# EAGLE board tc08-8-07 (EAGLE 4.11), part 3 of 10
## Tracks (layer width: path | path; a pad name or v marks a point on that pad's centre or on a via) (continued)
DB_03\  (via drill 0.61) (continued)
  Bottom 0.254: v309.28,75.87 309.92,76.5 310.55,76.5 313.41,79.36 313.41,84.44 v314.36,84.44 | v318.49,88.57 321.66,91.74 322.3,91.74 v323.25,92.7 | v328.97,98.73 330.55,97.14 334.05,97.14 334.36,97.46 337.22,97.46 337.54,97.14 341.03,97.14 344.21,100.32 v344.21,101.91 | v353.41,116.83 353.41,119.37 354.68,119.37 v356.27,120.96 | v350.87,146.67 v353.73,146.67 | v350.56,172.07 349.92,172.71 346.75,172.71 346.11,173.34 346.11,177.47 347.06,177.47 B02.L1 347.38,178.42 347.06,178.42 v347.06,181.28 | v300.39,254.94 302.93,252.4 v306.11,252.4 | v305.47,248.59 308.01,246.05 315.63,246.05 318.81,242.87 323.57,242.87 327.06,239.38 333.09,239.38 334.68,237.8 v336.27,237.8
DB_04\  (via drill 0.61)
  Top 0.254: 295.31,232.08 295.31,248.27 296.58,249.54 296.58,253.35 A06.J1 | 295.31,232.08 295.31,220.97 296.26,220.02 296.26,205.09 295.63,204.46 295.63,177.15 294.99,176.52 294.99,163.5 295.31,163.18 295.31,142.86 295.63,142.55 295.63,137.78 295.31,137.46 295.31,119.69 294.99,119.37 294.99,88.89 296.26,87.62 296.26,71.43 295.31,70.47 295.31,56.82 296.26,55.87 296.26,51.74 296.58,51.42 D06.J1 | v358.18,192.08 358.49,192.39 358.49,194.61 358.18,194.93 358.18,199.06 358.81,199.7 358.81,200.33 354.05,205.09 v354.05,210.17 | v330.87,210.81 331.19,211.12 331.19,221.92 329.28,223.83 v329.28,226.68 | v295.63,232.08 295.31,232.08
  Bottom 0.254: v358.18,192.08 361.67,192.08 361.67,188.9 359.13,186.36 359.13,182.87 362.3,179.69 364.84,179.69 364.84,167.63 363.57,166.36 349.29,166.36 348.33,165.4 B02.R1 | v354.05,210.17 353.73,209.86 331.82,209.86 v330.87,210.81 | v329.28,226.68 328.97,227 317.22,227 316.9,227.32 310.23,227.32 309.92,227 304.52,227 304.2,227.32 301.98,227.32 297.22,232.08 v295.63,232.08
DB_05\  (via drill 0.61)
  Top 0.254: v306.11,55.55 308.33,57.77 308.33,62.85 308.01,63.17 308.01,64.44 v310.23,66.66 | v334.05,117.78 333.73,118.1 333.73,123.18 334.36,123.81 v334.36,124.13 | v350.24,159.69 350.56,160.01 350.56,161.28 B02.S1 350.56,162.55 350.56,165.09 v350.24,165.4 | v288.01,253.35 286.1,255.26 286.1,280.66 288.01,282.56 v288.01,288.6 | v368.65,282.56 369.61,281.61 v369.61,250.81 | v361.03,243.83 359.13,241.92 359.13,240.65 359.76,240.02 v359.76,237.48
  Route2 0.254: v310.23,66.66 311.82,68.25 311.82,70.16 314.36,72.69 314.36,75.24 315,75.87 315,82.54 315.31,82.86 315.31,86.35 317.22,88.25 317.22,98.41 319.44,100.63 319.76,100.63 321.03,101.91 321.03,102.22 322.3,103.49 322.3,104.44 329.6,111.75 329.6,113.33 v334.05,117.78 | v334.36,124.13 334.36,125.72 332.78,127.3 332.78,129.21 333.09,129.53 333.09,135.88 339.44,142.23 339.44,147.62 345.48,153.66 345.48,154.61 350.24,159.37 v350.24,159.69 | v360.08,193.03 360.08,192.08 v358.18,190.17 | v350.24,165.4 v357.22,172.39
  Route15 0.254: v359.76,237.48 356.59,234.3 358.49,232.4 358.49,227.64 v360.08,226.05 | v358.18,221.92 361.99,218.11 361.99,204.46 v365.48,200.96
  Bottom 0.254: v306.11,55.55 305.15,55.55 305.15,50.79 300.39,46.03 298.8,46.03 297.53,44.75 D06.L1 | v288.01,253.35 289.28,253.35 289.28,249.86 288.96,249.54 288.96,247.32 290.23,246.05 294.99,246.05 296.26,247.32 A06.L1 | v288.01,288.6 288.33,288.91 321.66,288.91 321.98,288.6 362.62,288.6 v368.65,282.56 | v369.61,250.81 369.61,241.92 369.92,241.61 369.92,240.33 368.65,240.33 367.7,241.29 367.7,243.51 364.53,243.51 364.21,243.19 362.94,243.19 362.3,243.83 v361.03,243.83 | v360.08,226.05 360.08,223.51 359.76,223.51 v358.18,221.92 | v365.48,200.96 365.48,198.43 360.08,198.43 358.81,197.15 358.81,193.03 v360.08,193.03 | v358.18,190.17 355.64,187.63 355.64,173.66 355.95,173.66 v357.22,172.39
DB_06\  (via drill 0.61)
  Top 0.254: v292.77,6.97 292.77,7.29 301.34,15.86 301.34,35.55 300.07,36.82 D06.M1 | v3.85,40.95 2.89,41.9 2.89,222.55 3.53,223.19 3.53,248.91 2.26,250.18 2.26,267.64 2.89,268.28 2.89,269.55 v2.58,269.86 | v130.53,296.22 138.47,296.22 138.47,296.53 139.1,297.17 142.28,297.17 142.28,277.17 143.23,276.21 143.23,272.4 v144.82,270.81 | v155.61,270.18 157.52,270.18 157.83,270.5 159.1,270.5 159.1,269.23 160.37,267.96 165.77,267.96 165.77,267.64 167.36,266.05 168.63,266.05 168.63,273.99 170.85,276.21 170.85,293.99 171.17,294.31 176.57,294.31 176.57,284.47 v184.19,276.85 | v189.58,277.8 197.2,277.8 197.52,278.12 209.59,278.12 v209.59,276.53 | v260.07,286.69 259.43,286.05 259.43,275.9 v259.12,275.58 | v267.69,271.77 v268.96,273.04 | v343.25,198.11 342.94,198.43 342.94,200.33 345.79,203.19 345.79,205.73 346.11,206.05 346.11,210.17 345.16,211.12 v345.16,222.87
  Route2 0.254: v184.19,276.85 184.5,276.85 185.14,277.48 189.27,277.48 v189.58,277.8 | v278.17,270.18 278.17,268.91 276.58,267.32 276.58,262.56 v274.99,260.97
  Route15 0.254: v209.59,276.53 212.76,279.7 228.95,279.7 239.75,290.5 242.92,287.32 242.92,286.69 v241.97,285.74 | v259.12,275.58 261.34,273.36 v261.66,273.36 | v287.37,259.07 298.17,248.27 298.17,246.68 299.76,245.1 A06.M1
  Bottom 0.254: v292.77,6.97 292.45,6.66 275.94,6.66 275.63,6.34 261.02,6.34 259.75,5.07 232.13,5.07 230.22,6.97 223.56,6.97 222.92,6.34 38.45,6.34 v3.85,40.95 | v2.58,269.86 2.58,292.72 52.42,292.72 53.38,293.68 63.85,293.68 64.49,293.04 81.32,293.04 82.59,294.31 97.51,294.31 98.14,294.94 103.54,294.94 104.18,294.31 128.62,294.31 v130.53,296.22 | v144.82,270.81 145.13,271.13 154.66,271.13 v155.61,270.18 | v241.97,285.74 242.61,286.37 248.32,286.37 248.64,286.69 v260.07,286.69 | v261.66,273.36 261.97,273.04 263.24,273.04 264.51,271.77 v267.69,271.77 | v268.96,273.04 270.23,271.77 273.4,271.77 274.04,272.4 275.94,272.4 v278.17,270.18 | v274.99,260.97 276.9,259.07 v287.37,259.07 | v343.25,198.11 343.25,194.93 340.08,191.76 340.08,189.22 341.35,187.95 343.57,187.95 343.89,187.63 B02.H2 | v345.16,222.87 343.25,224.78 340.71,224.78 335,230.49 330.87,230.49 330.55,230.81 328.65,230.81 328.33,231.13 326.74,231.13 325.79,230.18 316.27,230.18 315.95,229.86 314.68,229.86 313.41,228.59 312.14,228.59 300.39,240.33 300.39,243.83 A06.M1
DB_07\  (via drill 0.61)
  Top 0.254: D06.P1 299.76,35.55 299.12,36.18 299.12,40.31 298.8,40.63 298.8,46.98 298.17,47.61 298.17,56.5 298.8,57.14 298.8,66.03 298.49,66.35 298.49,75.87 300.07,77.46 300.07,90.16 298.8,91.43 v298.8,183.18 298.8,209.22 300.07,210.49 300.07,223.51 298.8,224.78 298.8,232.71 299.76,233.67 299.76,237.48 A06.P1
  Bottom 0.254: v298.8,183.18 301.03,183.18 301.66,182.55 309.92,182.55 310.87,183.5 313.41,183.5 314.04,182.87 339.76,182.87 340.71,183.82 B02.J2
DB_08\  (via drill 0.61)
  Top 0.254: v294.36,11.42 298.8,15.86 298.8,22.85 299.12,23.16 299.12,27.29 299.76,27.93 D06.S1 | v100.68,14.59 98.14,17.13 98.14,154.93 98.46,155.24 98.46,157.47 98.14,157.79 98.14,202.24 97.83,202.55 97.83,205.41 98.46,206.05 98.46,227.32 98.14,227.64 98.14,272.09 97.83,272.4 97.83,275.26 98.46,275.9 v98.46,292.09 | v294.04,294.94 295.95,293.04 295.95,273.99 295.63,273.67 295.63,260.97 295.31,260.66 295.31,258.43 298.17,255.58 298.17,251.77 297.85,251.45 297.85,248.59 298.17,248.27 298.17,241.92 298.49,241.61 v298.49,233.67 | v356.91,169.85 355.95,168.9 355.95,163.82 356.27,163.5 356.27,162.86 355.95,162.55 355.95,158.74 v357.54,157.15 | v372.46,223.19 371.83,223.83 371.83,245.42 373.1,246.68 373.1,279.39 v370.24,282.24
  Route15 0.254: v347.06,169.85 345.79,171.12 341.98,171.12 B02.N2
  Bottom 0.254: v294.36,11.42 293.41,10.46 273.09,10.46 272.77,10.15 260.07,10.15 258.16,8.24 233.72,8.24 231.81,10.15 221.97,10.15 221.33,9.51 105.76,9.51 v100.68,14.59 | v98.46,292.09 98.78,291.77 129.89,291.77 131.48,293.36 144.82,293.36 145.13,293.04 173.71,293.04 174.34,293.68 203.24,293.68 203.55,293.36 206.09,293.36 206.41,293.68 208.95,293.68 210.86,295.58 230.54,295.58 231.49,294.63 234.35,294.63 234.99,295.26 267.37,295.26 268.96,296.85 292.14,296.85 v294.04,294.94 294.36,294.63 357.86,294.63 v370.24,282.24 | v298.49,233.67 299.76,232.4 A06.S1 | v356.91,169.85 v347.06,169.85 | v357.54,157.15 358.81,155.88 361.67,155.88 373.42,167.63 373.42,223.19 v372.46,223.19
DB_09\  (via drill 0.61)
  Top 0.254: v314.04,78.73 314.36,79.05 v314.36,83.17 | v350.56,119.05 350.87,119.37 350.87,121.91 349.6,123.18 349.6,126.67 v350.24,127.3 | v343.89,158.1 344.84,159.05 v344.84,160.33 | v318.17,268.28 320.39,266.05 320.39,247.32 v326.74,240.97 | v340.4,214.62 v340.4,218.11
  Route2 0.254: v314.04,78.73 310.23,74.92 309.28,74.92 308.65,74.28 305.79,74.28 305.15,73.65 304.2,73.65 296.58,66.03 295.95,66.03 293.72,63.81 291.18,63.81 D06.D2 | v325.79,90.47 342.62,107.3 342.62,111.11 v350.56,119.05 | v340.4,214.62 340.4,212.71 338.81,211.12 338.81,208.9 336.9,207 336.9,200.65 333.73,197.47 333.73,195.25 v334.36,194.61
  Route15 0.254: v320.39,89.21 v314.36,83.17 | v350.24,127.3 349.29,128.26 349.29,152.71 v343.89,158.1 | v344.84,160.33 347.7,163.18 346.43,164.45 346.43,166.04 344.84,167.63 B02.P2 | v326.74,240.97 326.74,238.75 336.59,228.9 336.59,221.92 v340.4,218.11 | v334.36,194.61 334.36,193.03 336.27,191.12 336.27,185.73 341.67,180.33 v341.98,180.33
  Bottom 0.254: v320.39,89.21 321.66,90.47 v325.79,90.47 | v318.17,268.28 296.58,268.28 295.95,267.64 291.82,267.64 291.18,267 A06.D2 | v341.98,180.33 342.3,180.01 342.94,180.01 343.25,179.69 343.25,168.9 344.21,168.9 B02.P2
DB_10\  (via drill 0.61)
  Top 0.254: v293.41,64.76 293.41,60.95 D06.E2 | v302.61,84.44 302.61,87.62 301.98,88.25 301.98,91.11 v302.3,91.43
  Route2 0.254: v302.3,91.43 302.3,92.38 304.52,94.6 304.52,99.05 308.65,103.18 308.65,106.99 307.38,108.25 307.38,109.21 311.5,113.33 311.5,118.1 324.52,131.11 324.52,132.7 330.87,139.05 330.87,139.37 331.51,140.01 332.14,140.01 338.49,146.36 338.49,147.62 342.62,151.75 342.62,153.34 344.21,154.93 B02.U2 344.84,156.2 346.11,157.47 346.11,159.05 346.43,159.37 346.43,165.72 350.24,169.53 350.56,169.53 351.51,170.49 v351.51,173.02
  Route15 0.254: v293.41,64.76 293.41,65.08 292.14,66.35 292.14,72.06 290.55,73.65 290.55,76.5 v288.33,78.73 | v297.85,258.11 297.85,255.89 302.93,250.81 302.93,249.86 304.84,247.96 304.84,245.42 v304.2,244.78 | v306.74,239.7 314.36,232.08 314.36,230.81 314.68,230.49 314.68,227 316.27,225.41 317.22,225.41 321.66,220.97 324.84,220.97 326.74,219.06 326.74,215.57 327.06,215.25 327.06,209.22 330.24,206.05 330.24,204.77 332.46,202.55 332.46,201.6 342.62,191.44 342.62,186.99 348.02,181.6 348.02,179.69 352.14,175.56 352.14,173.66 v351.51,173.02
  Bottom 0.254: v288.33,78.73 294.36,78.73 298.8,83.17 299.44,83.17 300.07,82.54 300.07,80.63 298.8,80.63 298.17,80 298.17,78.73 300.71,78.73 301.66,79.68 301.66,84.44 v302.61,84.44 | v297.85,258.11 298.17,258.43 298.49,258.43 298.49,260.66 297.22,261.93 295.63,261.93 294.36,263.19 A06.E2 | v304.2,244.78 304.2,242.24 v306.74,239.7
DB_11\  (via drill 0.61)
  Top 0.254: v302.3,97.78 301.98,98.1 301.98,103.81 v302.3,104.13 | v301.03,260.02 301.98,260.97 v301.98,262.88 | v329.6,261.93 330.24,261.29 v330.24,246.68 | v341.35,146.99 B02.V2
  Route2 0.254: v302.3,97.78 301.34,96.83 301.34,91.43 293.09,83.17 293.09,81.9 288.96,77.77 288.96,67.93 288.64,67.61 288.64,66.03 288.33,65.71 288.33,62.53 288.01,62.22 293.41,56.82 293.41,54.6 D06.H2 | v302.3,104.13 302.3,105.08 304.52,107.3 304.52,111.43 310.55,117.46 310.55,118.1 321.66,129.21 321.66,130.8 330.24,139.37 330.24,139.69 331.82,141.27 332.14,141.27 333.41,142.55 333.41,143.18 336.59,146.36 336.59,147.31 341.03,151.75 B02.V2 | v350.56,192.08 352.78,189.85 352.14,189.22 352.14,183.82 358.49,177.47 v357.86,176.83 | v354.37,162.23 350.56,158.42 350.56,157.15 346.11,152.71 346.11,151.75 v341.35,146.99
  Route15 0.254: v330.24,246.68 330.24,236.21 337.22,229.22 337.22,228.27 339.44,226.05 339.44,220.65 343.89,216.21 343.89,214.3 344.52,213.67 344.52,213.03 343.25,211.76 342.62,211.76 339.13,208.27 346.75,200.65 346.75,199.7 348.97,197.47 348.97,193.66 v350.56,192.08 | v357.86,176.83 357.86,175.88 358.49,175.25 358.49,167.63 354.05,163.18 354.05,162.55 v354.37,162.23
  Bottom 0.254: v301.03,260.02 298.17,257.16 A06.H2 | v301.98,262.88 304.2,265.1 314.68,265.1 317.85,261.93 v329.6,261.93
DF  (via drill 0.61)
  Top 0.254: v182.92,27.29 181.65,28.56 181.65,30.78 181.33,31.1 181.33,46.03 v181.96,46.66 | v130.53,52.06 129.89,51.42 v129.89,45.39 | v45.12,252.4 44.8,252.72 44.8,261.93 45.76,262.88 A26.E1 | v109.89,241.61 107.67,243.83 v107.67,263.19 | v61.31,263.51 v63.85,266.05
  Route2 0.254: v222.29,31.1 v217.52,26.34 | v215.94,244.78 v220.38,249.23
  Route15 0.254: v223.87,248.91 227.05,245.73 230.86,245.73 237.21,239.38 241.02,239.38 241.97,238.43 242.29,238.43 A10.P2 | v214.03,244.14 213.4,244.14 211.81,245.73 203.87,245.73 196.25,238.11 v195.62,238.75 | v185.77,236.52 185.46,236.52 184.82,237.16 183.55,237.16 v180.38,240.33
  Bottom 0.254: v222.29,31.1 226.1,31.1 226.41,31.42 D11.R2 | v217.52,26.34 217.21,26.66 208.63,26.66 208.32,26.98 206.09,26.98 205.78,26.66 195.93,26.66 195.62,26.98 193.39,26.98 193.08,26.66 183.55,26.66 v182.92,27.29 | v181.96,46.66 181.65,46.34 146.4,46.34 140.69,52.06 v130.53,52.06 | v129.89,45.39 129.58,45.71 68.93,45.71 42.9,71.74 6.39,71.74 3.53,74.6 3.53,246.37 13.37,246.37 16.55,249.54 40.68,249.54 42.58,251.45 44.17,251.45 v45.12,252.4 | v223.87,248.91 223.56,249.23 v220.38,249.23 | v215.94,244.78 215.3,244.14 v214.03,244.14 | v195.62,238.75 193.71,236.84 189.9,236.84 189.27,237.48 187.04,237.48 186.09,236.52 v185.77,236.52 | v180.38,240.33 180.06,240.02 175.3,240.02 173.71,241.61 172.12,241.61 170.53,240.02 111.48,240.02 v109.89,241.61 | v107.67,263.19 106.08,264.78 84.81,264.78 81.63,267.96 73.06,267.96 70.52,265.42 64.49,265.42 v63.85,266.05 | v61.31,263.51 61.31,265.42 60.04,265.42 59.41,266.05 56.87,266.05 56.23,265.42 54.33,265.42 54.01,265.74 50.2,265.74 48.3,263.83 46.71,263.83 A26.E1
DF\  (via drill 0.61)
  Top 0.254: v228,34.91 228.32,35.23 228.32,41.26 v228,41.58 | v225.46,44.12 v225.46,41.58 | v215.94,44.44 215.62,44.75 215.62,45.07 v214.67,46.03 | v208.32,46.34 v207.05,47.61 | v141.64,45.71 140.05,45.71 140.05,58.72 139.42,59.36 139.42,65.71 139.1,66.03 139.1,66.35 v138.15,67.3 | v129.58,70.16 129.89,70.47 129.89,75.55 128.31,77.14 v128.31,81.9 | v126.4,83.81 126.72,84.13 126.72,95.87 v124.5,98.1 | v122.59,100 120.37,102.22 120.37,110.48 v120.05,110.8 | v274.99,229.22 269.28,234.94 v269.28,236.21 | v259.12,238.11 257.21,238.11 v257.21,235.26 | v246.1,225.41 245.15,224.46 245.15,223.19 244.83,222.87 244.83,221.6 245.78,220.65 v245.78,215.25 | v239.11,212.71 238.8,212.39 v238.8,205.73 | v312.77,216.52 B05.A1
  Route2 0.254: v132.12,111.43 132.75,111.43 141.64,120.32 141.64,122.22 163.55,144.13 164.82,144.13 181.96,161.28 181.96,162.86 182.92,163.82 183.23,163.82 185.77,166.36 192.12,166.36 201.65,175.88 203.24,175.88 204.51,177.15 206.73,177.15 208.32,175.56 208.63,175.56 209.9,174.3 209.9,173.02 v211.17,171.76 | v309.92,219.38 v312.77,216.52 | v246.1,225.41 v251.81,231.13 | v238.8,205.73 238.8,205.41 235.62,202.24 235.62,200.96 235.3,200.65 235.3,189.85 v233.08,187.63
  Route15 0.254: v211.17,171.76 216.57,177.15 215.62,178.11 215.62,178.42 v210.86,183.18 | v277.85,224.46 276.9,225.41 276.9,227.32 v274.99,229.22 | v229.91,185.73 228.32,184.14 228.32,183.5 227.05,182.23 224.51,182.23 223.24,183.5 221.65,183.5 221.33,183.82 B12.J1
  Bottom 0.254: v225.46,41.58 v228,41.58 | v225.46,44.12 223.87,45.71 217.21,45.71 v215.94,44.44 | v214.67,46.03 214.35,46.34 v208.32,46.34 | v207.05,47.61 205.78,46.34 191.49,46.34 191.17,46.66 186.73,46.66 185.77,45.71 v141.64,45.71 | v138.15,67.3 136.88,68.57 131.16,68.57 v129.58,70.16 | v128.31,81.9 v126.4,83.81 | v124.5,98.1 v122.59,100 | v120.05,110.8 121.64,112.38 129.26,112.38 130.21,111.43 v132.12,111.43 | v210.86,183.18 211.17,182.87 215.3,182.87 216.57,184.14 B12.J1 | v228,34.91 D11.P2 | v309.92,219.38 309.6,219.7 307.69,219.7 303.88,223.51 295.95,223.51 294.68,222.24 292.45,222.24 290.87,223.83 278.48,223.83 v277.85,224.46 | v269.28,236.21 268.64,236.84 260.39,236.84 v259.12,238.11 | v257.21,235.26 253.08,231.13 v251.81,231.13 | v245.78,215.25 244.19,213.67 240.07,213.67 v239.11,212.71 | v233.08,187.63 231.18,185.73 v229.91,185.73
DTB_00  (via drill 0.61)
  Top 0.254: v255.94,63.49 257.53,65.08 257.53,73.65 260.39,76.5 260.39,91.74 260.7,92.06 260.7,94.28 262.61,96.19 262.61,97.14 263.24,97.78 263.24,125.72 v262.93,126.03 | v53.06,282.56 53.06,277.17 52.74,276.85 A25.A2 | v232.13,285.42 232.13,253.04 232.45,252.72 232.45,249.86 231.49,248.91 231.49,227.95 231.18,227.64 231.18,226.36 231.49,226.05 231.49,207 231.81,206.68 231.81,198.11 231.49,197.79 231.49,169.85 233.4,167.95 233.4,166.99 234.99,165.4 234.99,157.47 234.67,157.15 234.67,147.31 235.62,146.36 235.62,143.81 235.3,143.5 235.3,142.23 v236.26,141.27 | v247.05,131.75 247.37,132.07 247.37,138.1 246.42,139.05 C10.B1
  Bottom 0.254: v262.93,126.03 262.93,129.53 262.29,129.53 C09.E1 261.34,130.48 260.7,131.11 256.58,131.11 255.94,131.75 v247.05,131.75 | v255.94,63.49 D09.D2 | v53.06,282.56 54.01,283.51 57.19,283.51 58.46,282.24 134.66,282.24 136.24,283.83 140.05,283.83 140.37,283.51 185.46,283.51 186.73,284.79 188,284.79 188.63,284.15 210.22,284.15 210.86,284.79 217.84,284.79 218.16,285.1 231.81,285.1 v232.13,285.42 | v236.26,141.27 236.57,140.96 241.02,140.96 242.29,139.69 C10.B1
DTB_00\  (via drill 0.61)
  Top 0.254: v254.04,133.65 254.04,137.46 254.99,138.42 v254.99,139.37 | v267.37,211.12 v267.37,207.95 | v264.2,224.46 266.1,226.36 267.37,226.36 267.37,226.68 267.69,227 267.69,228.9 267.05,229.54 267.05,245.1 v268.64,246.68 | v268.64,255.26 267.05,255.26 v267.05,259.07 | v291.82,263.83 291.82,267.96 291.18,268.59 v291.18,269.86 | v292.77,271.45 294.99,273.67 v294.99,281.29 | v347.38,280.98 352.46,280.98 352.46,258.43 355.64,255.26 v355.64,253.35 | v347.38,244.78 347.06,244.46 347.06,242.56 346.11,241.61 346.11,239.38 346.43,239.06 346.43,235.57 346.11,235.26 346.11,233.99 v346.43,233.67
  Route2 0.254: v249.59,127.3 252.45,130.16 252.45,131.43 253.72,132.7 253.72,133.34 v254.04,133.65 | v254.99,139.37 254.99,140.32 257.21,142.55 257.21,149.21 253.72,152.71 253.72,153.66 248.64,158.74 249.91,160.01 249.91,160.64 250.54,161.28 250.54,185.09 255.31,189.85 255.31,191.12 260.07,195.89 260.07,200.33 267.37,207.63 v267.37,207.95 | v263.24,217.48 261.34,219.38 262.61,220.65 262.61,222.87 v264.2,224.46 | v355.64,253.35 347.38,245.1 v347.38,244.78 | v346.43,233.67 345.48,234.62 347.38,236.52 348.02,236.52 352.46,232.08 352.46,227 354.68,224.78 352.78,222.87 352.78,217.79 351.51,216.52 351.51,207.31 351.19,207 B02.A1
  Route15 0.254: v274.99,247 v277.85,249.86
  Bottom 0.254: v249.59,127.3 251.18,125.72 257.21,125.72 258.16,126.67 C09.F1 | v267.37,211.12 267.37,212.08 263.24,216.21 v263.24,217.48 | v268.64,246.68 268.96,246.37 274.36,246.37 v274.99,247 | v277.85,249.86 272.45,255.26 v268.64,255.26 | v267.05,259.07 267.69,259.7 268.96,259.7 271.18,261.93 289.91,261.93 v291.82,263.83 | v291.18,269.86 v292.77,271.45 | v294.99,281.29 295.31,280.98 v347.38,280.98
DTB_01  (via drill 0.61)
  Top 0.254: v250.86,47.93 250.54,48.25 250.54,67.3 251.18,67.93 251.18,79.68 250.86,80 250.86,84.13 251.18,84.44 251.18,93.65 250.54,94.28 250.54,100 247.37,103.18 247.37,121.91 v247.05,122.22 | v49.57,278.75 49.57,273.67 A25.B2 | v225.46,280.66 225.14,280.34 225.14,220.33 226.41,219.06 226.41,205.41 225.14,204.14 225.14,157.15 226.1,156.2 226.1,153.34 225.78,153.02 225.78,122.86 v226.41,122.22
  Bottom 0.254: v250.86,47.93 254.99,47.93 D09.K2 | 248,123.18 248.32,123.49 248.64,123.49 C10.H1 C09.H2 | v247.05,122.22 248,123.18 | v49.57,278.75 50.52,279.7 135.93,279.7 137.51,281.29 138.78,281.29 139.1,280.98 211.81,280.98 212.44,281.61 216.89,281.61 218.16,280.34 225.14,280.34 v225.46,280.66 | v226.41,122.22 226.73,121.91 244.19,121.91 245.46,123.18 248,123.18
DTB_01\  (via drill 0.61)
  Top 0.254: v279.75,135.24 279.44,135.56 279.44,137.78 279.75,138.1 279.75,142.23 279.44,142.55 279.44,143.5 v280.71,144.77 | v305.15,207.63 305.79,207.63 306.11,207.95 308.65,207.95 v308.65,207
  Route2 0.254: v261.66,120.96 261.66,121.59 267.37,127.3 269.91,127.3 277.21,134.61 279.12,134.61 v279.75,135.24 | v265.47,174.93 265.47,176.2 269.59,180.33 269.59,186.68 274.04,191.12 274.04,191.44 274.99,192.39 275.31,192.39 279.12,196.2 279.12,200.33 279.44,200.65 279.44,201.28 v288.33,210.17 | v297.22,210.49 300.07,207.63 v305.15,207.63 | v318.49,198.11 319.76,196.84 319.44,196.52 319.44,195.89 321.03,194.3 321.35,194.61 321.98,194.61 322.62,193.98 322.93,194.3 323.89,194.3 v331.51,201.92
  Route15 0.254: v280.71,144.77 280.71,147.62 273.4,154.93 273.4,161.28 267.05,167.63 267.05,168.26 266.1,169.21 266.1,170.17 267.37,171.44 266.74,172.07 266.74,173.66 v265.47,174.93 | v308.65,207 310.23,207 312.77,204.46 313.09,204.46 313.73,203.82 313.73,201.92 315.31,200.33 316.27,200.33 v318.49,198.11
  Bottom 0.254: v261.66,120.96 260.07,119.37 258.16,119.37 257.21,120.32 255.62,120.32 255.31,120 253.4,120 253.08,120.32 C09.J2 | v288.33,210.17 289.28,211.12 296.58,211.12 v297.22,210.49 | v331.51,201.92 336.59,201.92 337.86,203.19 339.44,203.19 340.71,201.92 341.98,201.92 342.94,202.87 347.06,202.87 B02.B1
DTB_02  (via drill 0.61)
  Top 0.254: v54.33,282.56 54.33,272.09 52.74,270.5 A25.C2 | v235.62,284.79 235.62,277.17 235.3,276.85 235.3,229.54 235.62,229.22 235.62,226.36 235.3,226.05 235.3,216.52 235.62,216.21 235.62,207.31 235.3,207 235.3,204.14 250.54,188.9 v250.54,147.62 | v260.07,147.31 260.07,134.93 260.7,134.29 260.7,116.19 v261.02,115.88 | v252.13,76.82 252.13,73.65 253.72,72.06 253.72,41.58 251.18,39.04 251.18,33.32 252.13,32.37 D09.R2 | v248.32,76.82 248.64,77.14 248.64,85.08 248.32,85.39 248.32,91.11 247.69,91.74 247.69,101.91 246.42,103.18 246.42,107.3 C10.N1
  Bottom 0.254: v54.33,282.56 54.65,282.24 57.5,282.24 58.14,281.61 134.97,281.61 136.56,283.2 139.74,283.2 140.05,282.88 185.77,282.88 187.04,284.15 187.68,284.15 188.31,283.51 210.54,283.51 211.17,284.15 218.16,284.15 218.48,284.47 233.72,284.47 234.03,284.79 v235.62,284.79 | v250.54,147.62 250.86,147.31 v260.07,147.31 | v261.02,115.88 259.75,114.61 259.43,114.61 C09.L1 258.16,113.97 255.31,113.97 251.18,109.84 248.32,109.84 246.73,108.25 C10.N1 | v248.32,76.82 v252.13,76.82
DTB_02\  (via drill 0.61)
  Top 0.254: v262.29,107.94 262.29,110.48 C09.M1 | v348.33,173.66 346.43,175.56 346.43,179.37 348.02,180.96 348.02,181.92 346.43,183.5 346.43,188.9 347.38,189.85 B02.F1
  Route2 0.254: v322.3,72.38 322.93,72.38 v333.41,82.86 | v346.11,82.86 347.06,83.81 347.06,84.44 350.56,87.94 351.19,87.94 354.05,90.79 354.05,92.38 357.22,95.55 357.22,96.51 364.84,104.13 364.84,107.62 365.16,107.94 365.16,111.43 365.8,112.07 365.8,139.69 v364.21,141.27
  Route15 0.254: v262.29,107.94 262.29,106.35 263.24,105.4 263.24,100.95 270.23,93.97 270.23,93.33 272.13,91.43 273.4,91.43 277.21,87.62 279.44,87.62 280.07,86.98 280.71,86.98 v283.88,83.81 | v299.12,79.68 303.25,75.55 307.06,75.55 307.69,74.92 315.31,74.92 v317.54,72.69 | v364.21,141.27 366.11,143.18 366.11,149.21 361.99,153.34 361.99,153.98 357.86,158.1 357.22,158.1 353.41,161.91 353.41,163.82 349.6,167.63 349.6,172.39 v348.33,173.66
  Bottom 0.254: v283.88,83.81 284.2,84.13 294.04,84.13 294.99,85.08 298.8,85.08 300.71,83.17 300.71,79.68 v299.12,79.68 | v317.54,72.69 318.49,71.74 321.66,71.74 v322.3,72.38 | v346.11,82.86 v333.41,82.86
DTB_03  (via drill 0.61)
  Top 0.254: v50.52,285.74 50.52,268.28 49.57,267.32 A25.D2 | v238.48,287.96 238.48,265.74 238.8,265.42 238.8,262.56 237.84,261.61 v237.84,203.19 | v236.57,201.6 236.89,201.6 248,190.49 248,183.18 248.32,182.87 248.32,181.92 248,181.6 248,157.15 247.37,156.52 247.37,140.32 v247.69,140.01 | v281.66,106.35 282.29,106.99 282.29,134.61 v283.88,136.2
  Bottom 0.254: v50.52,285.74 50.84,285.42 59.73,285.42 60.36,284.79 133.39,284.79 134.97,286.37 141.32,286.37 141.64,286.05 184.19,286.05 185.46,287.32 189.27,287.32 189.9,286.69 208.95,286.69 209.59,287.32 212.13,287.32 212.76,287.96 217.52,287.96 218.48,287.01 230.54,287.01 231.18,287.64 238.16,287.64 v238.48,287.96 | v237.84,203.19 237.84,201.6 v236.57,201.6 | v247.69,140.01 249.59,138.1 260.07,138.1 261.34,136.83 C09.C1 262.29,137.15 265.47,137.15 266.74,138.42 281.66,138.42 v283.88,136.2 | v281.66,106.35 281.34,106.03 257.21,106.03 256.26,105.08 C09.P2
DTB_03\  (via drill 0.61)
  Top 0.254: v350.56,182.87 350.56,186.68 B02.H1
  Route2 0.254: v284.52,81.9 285.47,81.9 292.45,88.89 294.04,88.89 294.99,89.84 294.99,96.19 v300.07,101.27 | v294.04,107.62 294.04,109.52 294.99,110.48 294.99,111.75 294.36,112.38 293.72,112.38 292.77,113.33 292.77,114.92 294.04,116.19 294.36,116.19 298.17,120 298.17,123.81 312.14,137.78 315.95,137.78 318.17,140.01 319.76,140.01 320.39,140.64 320.39,142.23 320.71,142.55 320.71,144.13 325.16,148.58 326.74,148.58 329.92,151.75 329.92,152.71 v331.19,153.98 | v328.97,156.2 328.97,157.15 336.27,164.45 336.27,168.58 v350.56,182.87
  Route15 0.254: v284.52,81.9 280.39,81.9 274.99,87.3 274.99,87.62 273.4,89.21 273.09,89.21 270.23,92.06 268.96,90.79 267.69,90.79 257.85,100.63 256.58,100.63 255.94,101.27 253.08,101.27 C09.R2 | v300.07,101.27 297.22,104.13 295.63,104.13 294.99,104.76 294.99,106.67 v294.04,107.62
  Bottom 0.254: v328.97,156.2 v331.19,153.98
DTB_04  (via drill 0.61)
  Top 0.254: v56.87,146.99 56.87,207.31 58.14,208.58 58.14,209.54 57.82,209.86 57.82,215.57 57.5,215.89 57.5,236.84 54.33,240.02 54.33,243.19 53.69,243.83 53.69,257.8 52.74,258.75 52.74,262.88 A25.E2 | v137.2,146.36 138.47,147.62 v138.47,149.85 | v196.89,151.43 v196.89,140.01 | v197.52,138.1 197.2,137.78 197.2,127.62 v198.16,126.67 | v234.67,99.68 234.67,113.97 v234.99,114.29 | v234.99,116.83 235.3,117.14 235.3,126.67 v235.62,126.99
  Bottom 0.254: v56.87,146.99 58.14,145.72 136.56,145.72 v137.2,146.36 | v138.47,149.85 138.78,149.53 146.72,149.53 147.36,148.89 175.3,148.89 177.52,151.12 185.46,151.12 185.77,151.43 188,151.43 188.31,151.12 196.57,151.12 v196.89,151.43 | v196.89,140.01 196.89,138.1 v197.52,138.1 | v198.16,126.67 199.11,125.72 211.17,125.72 213.71,128.26 235.62,128.26 | 235.62,128.26 251.81,128.26 253.72,130.16 C09.E2 | v234.67,99.68 260.39,99.68 261.34,98.73 C09.S1 | v234.99,116.83 v234.99,114.29 | 235.62,128.26 v235.62,126.99
DTB_04\  (via drill 0.61)
  Route2 0.254: v262.29,100 263.24,99.05 263.24,97.78 262.29,96.83 262.29,92.7 C09.U1 | v267.69,103.18 267.05,103.81 267.05,105.4 271.5,109.84 271.82,109.84 273.4,111.43 273.4,111.75 280.39,118.73 281.02,118.73 281.66,119.37 281.66,121.59 282.93,122.86 282.93,127.62 283.56,128.26 284.2,128.26 285.15,129.21 285.15,129.84 286.74,131.43 290.55,131.43 296.9,125.08 298.17,126.35 298.17,126.99 299.44,128.26 301.66,128.26 319.12,145.72 320.08,145.72 329.28,154.93 329.6,154.93 330.55,155.88 330.55,156.2 331.19,156.83 335,156.83 342.62,164.45 342.62,168.26 347.06,172.71 348.65,172.71 350.24,174.3 B02.M1
  Bottom 0.254: v262.29,100 262.29,102.86 267.37,102.86 v267.69,103.18
DTB_05  (via drill 0.61)
  Top 0.254: v54.96,225.73 54.33,226.36 54.33,238.11 51.15,241.29 51.15,248.59 50.52,249.23 50.52,258.75 49.57,259.7 A25.F2 | v58.77,221.92 58.46,221.6 58.46,210.17 58.77,209.86 58.77,208.27 57.5,207 57.5,147.62 v58.14,146.99 | v133.07,146.67 v133.07,87.62 | v201.01,84.44 202.92,86.35 202.92,95.87 203.55,96.51 203.55,99.36 v204.82,100.63 | v250.86,100.95 251.18,100.63 251.18,94.6 252.13,93.65 252.13,89.52 C09.V2 | v257.21,104.44 257.21,114.61 258.16,115.56 258.16,119.69 258.48,120 C09.J1
  Bottom 0.254: v58.77,221.92 v54.96,225.73 | v58.14,146.99 58.77,146.36 132.75,146.36 v133.07,146.67 | v133.07,87.62 134.66,86.03 145.77,86.03 146.09,86.35 182.92,86.35 184.19,85.08 184.82,85.08 185.46,85.71 195.93,85.71 197.2,84.44 v201.01,84.44 | v204.82,100.63 205.14,100.32 234.03,100.32 234.35,100.63 238.8,100.63 239.11,100.32 250.23,100.32 | 250.23,100.32 v250.86,100.95 | v257.21,104.44 257.21,102.54 256.58,102.54 254.35,100.32 250.23,100.32
DTB_05\  (via drill 0.61)
  Top 0.254: v363.26,93.65 362.62,94.28 362.62,97.46 362.3,97.78 362.3,125.4 362.94,126.03 362.94,126.99 v361.67,128.26
  Route2 0.254: v261.34,88.25 263.88,85.71 267.37,89.21 269.28,89.21 273.09,85.39 274.36,85.39 274.67,85.71 275.31,85.71 v280.07,80.95
  Route15 0.254: v292.77,79.68 294.99,79.68 298.49,83.17 299.76,83.17 305.79,89.21 311.19,83.81 312.46,83.81 314.04,82.22 316.9,82.22 322.3,87.62 326.11,87.62 333.09,80.63 335.95,80.63 v337.22,81.9 | v343.57,81.9 349.6,81.9 355.32,87.62 355.95,86.98 v356.27,86.98 | v361.67,128.26 361.35,128.26 359.76,129.84 359.76,132.07 355.64,136.2 355.64,137.78 357.86,140.01 357.86,141.27 359.76,143.18 359.45,143.5 359.45,145.08 349.29,155.24 349.29,166.99 348.97,167.31 348.97,169.85 348.02,170.8 B02.N1
  Bottom 0.254: v261.34,88.25 259.75,88.25 259.43,88.57 C09.V1 | v280.07,80.95 281.34,79.68 v292.77,79.68 | v337.22,81.9 337.54,82.22 343.25,82.22 v343.57,81.9 | v356.27,86.98 362.94,93.65 v363.26,93.65
DTB_06  (via drill 0.61)
  Top 0.254: v255.31,114.92 254.99,114.61 254.99,112.07 255.31,111.75 C09.M2 | v264.51,134.93 263.88,135.56 263.88,192.71 v264.2,193.03 | v36.23,255.58 35.28,254.62 35.28,145.4 35.6,145.08 35.6,140.64 35.28,140.32 35.28,72.38 35.6,72.06 35.6,70.79 35.28,70.47 v35.28,42.53 | v218.48,16.18 219.11,16.82 219.11,39.99 222.6,43.49 222.6,57.14 v224.19,58.72 | v227.68,74.28 228,74.6 228,80.95 v227.68,81.27 | v249.91,101.91 251.18,103.18 251.18,111.11 v251.5,111.43
  Route2 0.254: v228.64,64.12 228.64,73.33 v227.68,74.28 | v233.4,83.81 233.4,85.71 249.59,101.91 v249.91,101.91
  Route15 0.254: v262.29,119.69 264.51,121.91 264.51,125.72 263.88,126.35 263.88,129.21 263.24,129.84 263.24,133.65 v264.51,134.93
  Bottom 0.254: v262.29,119.69 259.43,116.83 257.21,116.83 v255.31,114.92 254.99,114.61 254.67,114.61 v251.5,111.43 | v264.2,193.03 263.88,193.34 262.61,193.34 B09.E1 | v36.23,255.58 50.52,255.58 51.79,256.85 A25.H2 | v35.28,42.53 61.63,16.18 109.26,16.18 110.21,15.23 179.74,15.23 180.38,14.59 216.89,14.59 v218.48,16.18 | v224.19,58.72 224.51,59.04 230.86,59.04 231.49,59.68 231.49,63.17 229.59,63.17 v228.64,64.12 | v227.68,81.27 226.73,82.22 226.73,83.81 v233.4,83.81
DTB_06\  (via drill 0.61)
  Top 0.254: v259.12,193.34 259.43,193.03 259.43,191.44 259.12,191.12 B09.F1 | v268.96,203.82 269.91,204.77 269.91,208.58 v268.32,210.17 | v302.61,218.74 304.52,220.65 304.52,224.46 303.88,225.09 v303.88,226.36 | v305.79,228.27 305.47,228.59 305.47,230.81 305.15,231.13 305.15,233.03 v307.06,234.94 | v319.76,236.52 320.39,235.89 v320.39,228.27 | v325.79,222.55 v325.79,218.74 | v346.11,217.79 347.06,216.84 347.06,211.12 v346.75,210.81 | v341.03,200.33 341.03,197.47 B02.D2
  Route2 0.254: v259.12,193.34 259.12,193.98 v268.96,203.82 | v303.88,226.36 v305.79,228.27 | v320.39,228.27 325.79,222.87 v325.79,222.55 | v346.75,210.81 346.75,210.49 342.94,206.68 342.94,202.24 v341.03,200.33
  Bottom 0.254: v268.32,210.17 267.05,210.17 262.29,214.93 262.29,218.43 269.28,218.43 269.91,219.06 278.48,219.06 280.07,217.48 298.49,217.48 299.76,218.74 v302.61,218.74 | v307.06,234.94 308.65,236.52 v319.76,236.52 | v325.79,218.74 326.11,219.06 341.35,219.06 342.62,217.79 v346.11,217.79
DTB_07  (via drill 0.61)
  Top 0.254: v9.88,252.08 9.24,251.45 v9.24,2.21 | v263.24,2.21 263.24,74.92 262.29,75.87 v262.29,90.16 | v259.12,91.43 260.07,92.38 260.07,94.6 260.7,95.24 260.7,103.18 261.66,104.13 C09.P1 261.66,105.4 261.66,106.67 v261.34,106.99 | v260.39,150.8 261.02,150.17 261.02,143.81 260.7,143.5 260.7,135.24 261.66,134.29 v261.66,132.7 | v258.16,128.58 257.53,127.94 257.53,115.88 255.94,114.29 v255.94,113.02
  Route2 0.254: v261.66,132.7 261.66,131.75 260.7,130.8 260.7,129.84 259.43,128.58 v258.16,128.58
  Bottom 0.254: v9.88,252.08 42.9,252.08 44.17,253.35 48.3,253.35 48.61,253.67 A25.J2 | v9.24,2.21 10.2,1.26 262.29,1.26 v263.24,2.21 | v262.29,90.16 261.66,90.79 259.75,90.79 v259.12,91.43 | v260.39,150.8 254.35,150.8 253.08,152.07 B09.V2 | v255.94,113.02 255.31,112.38 254.67,112.38 251.18,108.89 251.18,106.67 261.02,106.67 v261.34,106.99
DTB_07\  (via drill 0.61)
  Top 0.254: v259.12,154.61 259.12,153.02 B09.V1
  Route2 0.254: v259.12,154.61 267.05,162.55 267.05,163.82 278.17,174.93 278.17,175.25 284.2,181.28 285.79,181.28 286.74,182.23 290.55,182.23 298.17,189.85 298.17,190.49 299.44,191.76 301.34,191.76 303.57,193.98 303.57,194.61 308.01,199.06 309.6,199.06 318.17,207.63 v318.17,207.95 | v341.67,188.9 342.62,189.85 342.62,191.44 344.21,193.03 B02.E2
  Route15 0.254: v320.39,207.63 321.35,207.63 324.52,204.46 326.11,204.46 326.74,203.82 326.74,203.19 334.36,195.57 334.68,195.57 336.9,193.34 336.9,193.03 337.54,192.39 338.17,192.39 339.13,191.44 339.13,190.8 340.71,189.22 341.35,189.22 v341.67,188.9
  Bottom 0.254: v318.17,207.95 320.08,207.95 v320.39,207.63
DTB_08  (via drill 0.61)
  Top 0.254: v252.77,98.73 252.77,95.87 C09.T2 | v264.83,141.27 v264.83,148.26 | v52.74,253.04 52.74,251.45 A25.K2 | v53.69,264.78 v53.69,259.07 | v25.44,262.56 25.12,262.24 25.12,252.72 v20.36,247.96 | v10.83,77.14 13.05,74.92 v13.05,74.28 | v131.48,74.28 132.12,74.92 v132.12,78.09 | v161.64,67.93 161.64,56.82 167.04,51.42 v167.04,51.1 | v169.58,53.64 172.12,56.18 173.71,56.18 v173.71,56.82
  Route2 0.254: v252.77,98.73 252.77,100 253.72,100.95 253.72,107.3 256.89,110.48 256.89,121.27 262.61,126.99 263.24,126.99 266.42,130.16 266.42,135.24 262.61,139.05 v264.83,141.27 | v256.26,170.8 259.43,173.98 259.43,176.83 259.12,177.15 B09.L1 | v169.58,53.64 v167.04,51.1 | v211.49,63.17 212.13,63.17 217.21,68.25 221.02,68.25 225.14,72.38 225.14,73.01 227.37,75.24 230.22,75.24 248.32,93.33 250.23,93.33 251.81,94.92 C09.T2
  Route15 0.254: v264.83,148.26 264.83,150.8 263.88,151.75 263.88,161.91 263.56,162.23 263.56,163.18 262.29,164.45 262.29,165.09 256.58,170.8 v256.26,170.8 | v157.2,67.61 v146.4,78.41 | v186.09,58.09 188,60 191.81,56.18 194.35,56.18 195.62,54.92 v195.93,54.92 | v205.14,57.46 211.17,63.49 v211.49,63.17
  Bottom 0.254: v52.74,253.04 53.06,252.72 56.23,252.72 56.87,253.35 56.87,259.07 v53.69,259.07 | v53.69,264.78 50.2,264.78 47.66,262.24 25.75,262.24 v25.44,262.56 | v20.36,247.96 16.23,243.83 15.59,243.83 4.8,233.03 4.8,77.14 v10.83,77.14 | v13.05,74.28 13.37,74.6 131.16,74.6 v131.48,74.28 | v132.12,78.09 132.43,78.41 v146.4,78.41 | v157.2,67.61 157.52,67.93 v161.64,67.93 | v173.71,56.82 175.3,58.41 185.77,58.41 v186.09,58.09 | v195.93,54.92 196.25,55.23 202.6,55.23 204.82,57.46 v205.14,57.46
DTB_08\  (via drill 0.61)
  Top 0.254: v262.29,176.83 262.29,175.25 B09.M1 | v283.25,186.99 282.93,187.31 282.93,203.82 284.2,205.09 v284.52,205.09 | v301.66,212.39 304.2,209.86 304.2,206.05 306.11,204.14 v306.11,203.51 | v343.57,183.82 343.89,183.5 343.89,181.28 B02.K2
  Route2 0.254: v277.53,185.73 v271.5,179.69 | v341.67,185.73 v343.57,183.82
  Route15 0.254: v284.52,205.09 284.52,209.54 v282.61,211.44 | v306.11,203.51 306.74,203.51 309.92,200.33 310.55,200.33 321.66,189.22 334.68,189.22 v335,188.9
  Bottom 0.254: v262.29,176.83 262.61,176.52 268.32,176.52 v271.5,179.69 | v277.53,185.73 277.85,185.41 279.75,185.41 280.39,184.77 281.02,184.77 v283.25,186.99 | v282.61,211.44 283.56,212.39 v301.66,212.39 | v335,188.9 335.32,188.58 338.81,188.58 v341.67,185.73
DTB_09  (via drill 0.61)
  Top 0.254: v48.61,285.1 48.61,277.48 47.98,276.85 47.98,249.23 48.93,248.27 A25.L2 | v241.97,287.01 242.92,286.05 242.92,278.12 244.51,276.53 244.51,267.96 244.19,267.64 244.19,257.8 247.37,254.62 247.37,229.22 248,228.59 248,218.74 248.32,218.43 248.32,207.31 248,207 248,205.73 v248.96,204.77 | v254.35,190.17 254.35,180.33 254.67,180.01 254.67,179.06 254.35,178.74 254.35,173.98 254.99,173.34 254.99,169.21 255.31,168.9 B09.P2 | v261.66,195.25 261.66,199.38 B09.C1
  Bottom 0.254: v48.61,285.1 48.93,284.79 59.41,284.79 60.04,284.15 133.7,284.15 135.29,285.74 141.01,285.74 141.32,285.42 184.5,285.42 185.77,286.69 188.95,286.69 189.58,286.05 209.27,286.05 209.9,286.69 212.44,286.69 213.08,287.32 217.21,287.32 218.16,286.37 230.86,286.37 231.49,287.01 v241.97,287.01 | v248.96,204.77 251.81,201.92 256.58,201.92 258.16,200.33 261.34,200.33 B09.C1 | v254.35,190.17 258.48,194.3 260.7,194.3 v261.66,195.25
DTB_09\  (via drill 0.61)
  Top 0.254: v252.77,162.23 252.77,164.45 B09.R2
  Route2 0.254: v281.98,139.37 294.99,152.39 294.99,153.02 297.85,155.88 298.17,155.88 298.8,156.52 298.8,157.15 v303.25,161.59 | v311.19,161.59 313.41,159.37 316.27,162.23 317.54,162.23 318.49,163.18 322.62,163.18 v335,175.56
  Route15 0.254: v261.34,153.66 v252.77,162.23 | v265.47,153.98 267.05,153.98 280.71,140.32 281.02,140.32 v281.98,139.37
  Bottom 0.254: v261.34,153.66 261.66,153.98 v265.47,153.98 | v303.25,161.59 304.84,163.18 309.6,163.18 v311.19,161.59 | v335,175.56 335.32,175.88 339.13,175.88 340.71,177.47 B02.L2
DTB_10  (via drill 0.61)
  Top 0.254: v57.19,209.22 57.19,215.25 56.87,215.57 56.87,236.52 53.69,239.7 53.69,242.87 52.74,243.83 A25.M2 | v150.21,209.54 149.58,208.9 149.58,161.91 v151.17,160.33
  Bottom 0.254: v57.19,209.22 149.9,209.22 v150.21,209.54 | v151.17,160.33 151.48,160.01 169.26,160.01 169.9,160.64 247.37,160.64 248.96,159.05 251.81,159.05 B09.T2 253.08,159.05 254.35,160.33 260.07,160.33 261.34,161.59 B09.S1
DTB_10\  (via drill 0.61)
  Route2 0.254: v268.32,157.47 268.32,158.74 281.34,171.76 282.61,171.76 v285.15,174.3
  Route15 0.254: v300.39,172.71 300.39,172.39 302.61,170.17 302.93,170.17 303.57,169.53 v303.57,168.26 | v311.19,169.21 311.82,169.21 313.73,171.12 314.04,171.12 314.68,171.76 314.68,172.07 315.95,173.34 v318.49,170.8 | v331.19,169.85 334.68,169.85 337.54,166.99 339.13,166.99 340.71,165.4 B02.R2
  Bottom 0.254: v268.32,157.47 267.05,156.2 262.93,156.2 262.61,155.88 B09.U1 | v285.15,174.3 286.1,173.34 295.31,173.34 295.95,173.98 298.8,173.98 300.07,172.71 v300.39,172.71 | v303.57,168.26 304.84,169.53 310.87,169.53 v311.19,169.21 | v318.49,170.8 319.12,170.17 330.87,170.17 v331.19,169.85
DTB_11  (via drill 0.61)
  Top 0.254: v50.84,235.26 49.88,236.21 49.88,240.33 49.57,240.65 A25.N2 | v250.86,220.33 250.86,201.28 252.77,199.38 252.77,198.43 254.04,197.15 254.04,191.76 255.31,190.49 255.31,187.95 B09.H2 255.94,186.68 258.16,184.46 B09.J1
  Bottom 0.254: v50.84,235.26 53.06,233.03 79.41,233.03 84.81,227.64 85.44,227.64 92.75,220.33 199.11,220.33 199.43,220.65 211.17,220.65 211.81,221.29 212.44,221.29 213.71,220.02 250.54,220.02 v250.86,220.33
DTB_11\  (via drill 0.61)
  Top 0.254: v343.89,165.4 343.89,162.86 344.21,162.55 B02.S2 | v304.84,184.46 304.52,184.14 304.52,182.87 v302.3,180.64
  Route2 0.254: v321.98,187.31 321.03,187.31 315.63,192.71 313.41,190.49 311.5,190.49 307.06,186.04 306.42,186.04 v304.84,184.46 | v261.66,190.8 260.07,189.22 260.07,188.27 256.26,184.46 253.08,184.46 B09.J2
  Route15 0.254: v343.89,165.4 v321.98,187.31 | v299.76,179.37 299.44,179.37 294.04,184.77 293.41,184.77 v291.18,186.99 | v281.34,188.9 279.12,188.9 v278.17,187.95
  Bottom 0.254: v302.3,180.64 301.03,179.37 v299.76,179.37 | v291.18,186.99 290.23,186.04 286.42,186.04 283.56,188.9 v281.34,188.9 | v278.17,187.95 277.85,188.27 275.63,188.27 275.31,188.58 271.5,188.58 268.96,186.04 267.69,186.04 267.05,186.68 267.05,189.22 264.51,189.22 262.93,190.8 v261.66,190.8
DTF  (via drill 0.61)
  Top 0.254: v270.55,251.77 271.18,252.4 271.18,253.35 A08.J1 | v1.94,268.59 1.62,268.28 1.62,232.08 v1.94,231.76 | v36.23,76.82 37.82,75.24 v37.82,46.34 | v214.03,21.26 215.94,19.35 215.94,11.42 224.83,2.53 227.37,2.53 v227.37,14.27 | v232.45,14.27 233.08,14.91 233.08,18.4 D11.V1 | v167.68,254.3 164.82,254.3 164.82,254.62 164.18,255.26 159.1,255.26 159.1,243.19 v159.42,242.87 | v123.54,253.99 v123.54,260.02 | v95.29,263.19 94.97,263.51 94.97,269.86 87.67,277.17 87.67,287.01 77.51,297.17 55.28,297.17 v55.28,275.9
  Route15 0.254: v1.94,231.76 2.89,231.76 v10.83,223.83 | v220.38,244.14 219.43,244.14 218.79,243.51 218.48,243.51 214.35,239.38 213.4,239.38 v208.32,244.46 | v188.95,243.51 v184.5,247.96 | v178.47,247.96 176.25,245.73 v167.68,254.3 | v151.8,244.78 150.85,245.73 150.21,245.73 v143.55,252.4 | v134.66,254.62 131.8,251.77 v130.21,253.35
  Bottom 0.254: v270.55,251.77 269.59,251.77 266.1,255.26 262.29,255.26 253.4,246.37 248.32,246.37 244.51,242.56 226.1,242.56 224.51,244.14 A12.M1 223.24,244.14 v220.38,244.14 | v1.94,268.59 40.36,268.59 40.99,269.23 45.12,269.23 45.44,269.55 A26.C1 46.71,270.18 49.57,270.18 v55.28,275.9 | v10.83,223.83 6.07,219.06 6.07,85.71 27.34,85.71 v36.23,76.82 | v37.82,46.34 63.22,20.94 120.05,20.94 120.69,20.31 181.01,20.31 181.65,20.94 213.71,20.94 v214.03,21.26 | v227.37,14.27 v232.45,14.27 | v208.32,244.46 206.73,244.46 205.46,243.19 189.27,243.19 v188.95,243.51 | v184.5,247.96 183.55,248.91 179.42,248.91 v178.47,247.96 | v159.42,242.87 159.1,243.19 153.39,243.19 v151.8,244.78 | v143.55,252.4 143.23,252.72 136.88,252.72 134.97,254.62 v134.66,254.62 | v130.21,253.35 129.89,253.04 126.4,253.04 125.77,252.4 125.13,252.4 v123.54,253.99 | v123.54,260.02 121.32,262.24 96.24,262.24 v95.29,263.19
DTF\  (via drill 0.61)
  Top 0.254: v253.08,207 v256.58,203.51 | v197.2,38.09 195.93,39.36 195.93,43.17 196.57,43.8 v196.57,53.64 | v165.45,55.23 164.82,55.87 164.82,58.72 162.28,61.27 162.28,67.3 162.6,67.61 162.6,68.88 161.96,69.52 v161.96,70.79 | v154.34,101.91 152.75,103.49 152.75,109.84 v151.8,110.8 | v149.9,111.43 152.44,113.97 v152.44,117.78 | v167.99,133.34 168.63,133.97 v168.63,141.27 | v178.47,152.07 181.33,152.07 181.33,153.66 v182.92,155.24 | v194.98,167.31 194.35,167.95 194.35,170.49 194.03,170.8 194.03,172.71 v195.62,174.3
  Route2 0.254: v238.8,214.93 231.81,207.95 231.81,206.05 230.86,205.09 230.86,203.82 227.37,200.33 224.51,200.33 B12.C1 223.56,199.38 221.97,197.79 221.97,196.2 221.33,195.57 221.33,195.25 213.71,187.63 220.7,180.64 v220.7,179.69 | v287.37,190.8 v293.09,196.52 | v152.44,117.78 152.44,120.32 v156.88,124.77 | v163.87,129.21 v167.99,133.34 | v168.63,141.27 168.63,142.23 v178.47,152.07 | v182.92,155.24 v194.98,167.31
  Route15 0.254: v238.8,214.93 243.56,214.93 249.27,209.22 250.86,209.22 v253.08,207 | v277.53,200.96 277.53,200.65 v287.37,190.8 | v293.09,196.52 293.09,196.2 300.39,188.9 302.3,188.9 v313.09,178.11 | v223.56,19.35 220.7,16.5 218.48,18.72 216.57,18.72 214.98,20.31 210.22,20.31 208,22.53 208,23.48 209.9,25.39 v197.2,38.09 | v161.96,70.79 161.96,77.46 v160.69,78.73 | v160.69,83.81 160.69,87.94 164.5,91.74 v154.34,101.91
  Bottom 0.254: v256.58,203.51 258.48,201.6 276.9,201.6 v277.53,200.96 | v313.09,178.11 315.31,178.11 B04.L2 | v223.56,19.35 226.41,19.35 D11.V2 | v196.57,53.64 196.25,53.96 194.03,53.96 192.76,55.23 v165.45,55.23 | v160.69,83.81 v160.69,78.73 | v151.8,110.8 151.17,111.43 v149.9,111.43 | v156.88,124.77 159.74,127.62 159.74,128.89 163.55,128.89 v163.87,129.21 | v195.62,174.3 196.57,175.25 197.2,175.25 197.84,175.88 203.24,175.88 204.51,177.15 206.73,177.15 207.36,176.52 217.52,176.52 v220.7,179.69
DTSF  (via drill 0.61)
  Top 0.254: v232.13,226.68 232.13,207.31 232.76,206.68 v232.76,204.77
  Route2 0.254: v287.06,138.42 291.5,138.42 293.09,140.01 294.68,140.01 v296.58,138.1
  Route15 0.254: v232.13,226.68 224.51,234.3 222.6,234.3 222.29,234.62 221.33,234.62 A12.R1 | v232.76,204.77 230.54,202.55 240.7,192.39 241.34,192.39 v248.96,184.77 | v249.59,178.42 249.91,178.42 251.81,176.52 252.45,176.52 254.35,174.61 254.35,173.98 262.93,165.4 262.93,164.77 264.2,163.5 264.2,162.55 264.51,162.23 264.51,161.28 266.42,159.37 266.42,155.56 280.71,141.27 284.52,141.27 287.06,138.74 v287.06,138.42
  Bottom 0.254: v248.96,184.77 248.96,184.14 248.32,183.5 248.32,182.23 256.26,182.23 256.89,181.6 256.89,179.69 254.67,179.69 254.04,180.33 251.81,180.33 249.91,178.42 v249.59,178.42 | v296.58,138.1 296.9,138.42 303.88,138.42 307.69,142.23 312.46,142.23 C05.A1
EA_00\  (via drill 0.61)
  Top 0.254: 289.28,166.68 289.28,203.82 290.55,205.09 A06.V2 | 289.28,166.68 289.28,88.25 290.55,86.98 290.55,71.74 288.96,70.16 288.96,34.6 288.33,33.96 288.33,30.15 288.64,29.83 288.64,25.39 289.6,24.44 289.6,20.31 290.23,19.67 D06.V2 | 289.28,166.68 v290.23,166.68
  Bottom 0.254: v290.23,166.68 290.55,166.36 308.01,166.36 308.96,165.4 B05.R1
EA_01\  (via drill 0.61)
  Top 0.254: v291.82,2.84 291.82,19.67 290.55,20.94 D06.T2 | v5.75,9.51 6.07,9.83 6.07,73.01 4.8,74.28 4.8,77.46 5.43,78.09 5.43,177.15 4.8,177.79 4.8,180.96 5.43,181.6 5.43,249.86 4.16,251.13 4.16,266.37 4.8,267 4.8,288.28 4.48,288.6 v4.48,289.86 | v287.06,292.41 289.91,292.41 289.91,280.66 | 289.91,280.66 289.91,274.31 289.28,273.67 289.28,265.1 292.14,262.24 292.14,233.35 290.87,232.08 290.87,229.22 A06.T2 | v312.14,158.1 312.14,160.96 312.46,161.28 B05.S1 | v358.49,148.26 359.13,148.89 359.13,155.24 v360.72,156.83 | v370.56,214.62 370.88,214.93 370.88,218.74 370.56,219.06 370.56,246.05 371.19,246.68 v371.19,268.28 | 289.91,280.66 v290.87,280.66
  Route15 0.254: v312.14,158.1 317.22,153.02 317.22,150.17 v320.08,147.31
  Bottom 0.254: v291.82,2.84 291.5,2.53 266.1,2.53 264.2,4.43 261.97,4.43 260.7,3.16 231.18,3.16 229.91,4.43 226.41,4.43 225.78,5.07 224.51,5.07 223.87,4.43 12.1,4.43 10.83,5.7 9.88,5.7 6.07,9.51 v5.75,9.51 | v4.48,289.86 26.71,289.86 27.66,288.91 54.01,288.91 54.96,287.96 61,287.96 61.63,287.32 83.22,287.32 84.49,288.6 87.03,288.6 87.67,287.96 131.8,287.96 133.39,289.55 142.91,289.55 143.23,289.23 182.6,289.23 183.87,290.5 190.85,290.5 191.49,289.86 207.36,289.86 208,290.5 210.54,290.5 211.17,291.13 212.44,291.13 213.71,292.41 216.89,292.41 217.52,291.77 219.43,291.77 219.75,291.45 235.94,291.45 236.57,292.09 268.96,292.09 269.59,292.72 281.98,292.72 282.61,292.09 286.74,292.09 v287.06,292.41 | v320.08,147.31 323.89,147.31 325.16,148.58 346.43,148.58 346.75,148.26 v358.49,148.26 | v360.72,156.83 363.26,159.37 364.21,159.37 371.51,166.68 371.51,214.62 v370.56,214.62 | v371.19,268.28 364.53,274.94 360.4,274.94 356.27,279.07 348.02,279.07 346.75,280.34 291.18,280.34 v290.87,280.66
EA_02\  (via drill 0.61)
  Top 0.254: v363.26,26.66 367.07,26.66 367.07,34.28 366.43,34.91 366.43,60 367.7,61.27 367.7,62.53 367.07,63.17 367.07,73.01 368.02,73.97 368.02,74.92 368.97,75.87 368.97,76.5 368.34,77.14 368.34,98.41 368.97,99.05 368.97,105.4 369.29,105.72 369.29,108.25 369.92,108.89 369.92,111.43 369.61,111.75 369.61,126.03 368.97,126.67 368.97,143.5 369.61,144.13 369.61,200.01 369.92,200.33 369.92,209.86 368.97,210.81 368.97,220.02 v369.29,220.33 | v309.6,210.17 309.6,205.73 308.33,204.46 308.33,200.01 307.38,199.06 307.38,197.47 305.15,195.25 305.15,193.03 306.11,192.08 306.11,187.95 B05.H2
  Bottom 0.254: v363.26,26.66 349.92,26.66 349.6,26.98 347.38,26.98 347.06,26.66 340.71,26.66 337.86,23.8 327.38,23.8 324.2,26.98 295.63,26.98 294.36,28.25 D06.S2 | 311.19,220.33 308.01,220.33 297.22,231.13 294.04,231.13 A06.S2 | 311.19,220.33 v369.29,220.33 | v309.6,210.17 309.6,210.81 311.19,212.39 311.19,220.33
EF  (via drill 0.61)
  Top 0.254: v56.87,280.66 56.87,247 56.55,246.68 56.55,242.56 55.92,241.92 A25.N1 | v219.43,282.24 219.43,264.47 220.38,263.51 220.38,260.97 A12.F1 221.02,259.7 221.02,255.89 221.97,254.94 221.97,249.23 221.02,248.27 A12.L1
  Bottom 0.254: v56.87,280.66 57.19,280.34 135.61,280.34 137.2,281.93 139.1,281.93 139.42,281.61 211.49,281.61 212.13,282.24 v219.43,282.24 | A11.J1 230.22,253.99 224.19,247.96 221.33,247.96 A12.L1
EF\  (via drill 0.61)
  Top 0.254: v328.97,213.67 329.28,213.98 329.28,217.16 v330.24,218.11 | v336.27,239.06 336.59,239.38 336.59,247.32 336.27,247.64 336.27,248.91 335.95,249.23 335.95,253.04 336.27,253.35 336.27,257.16 327.06,266.37 v327.06,287.64 | v269.28,287.01 263.24,280.98 263.24,266.69 260.7,264.15 v260.7,255.89 | v242.29,253.35 v239.75,250.81
  Route2 0.254: v328.97,213.67 328.97,212.39 327.06,210.49 327.06,209.86 325.79,208.58 325.79,207 B04.A1 | v330.24,218.11 330.24,233.03 v336.27,239.06
  Route15 0.254: v252.45,256.53 250.23,254.3 v249.59,254.94
  Bottom 0.254: v327.06,287.64 326.74,287.96 292.77,287.96 291.82,287.01 v269.28,287.01 | v260.7,255.89 260.07,256.53 258.8,256.53 258.16,255.89 253.08,255.89 v252.45,256.53 | v249.59,254.94 249.27,255.26 245.46,255.26 243.56,253.35 v242.29,253.35 | v239.75,250.81 A11.K1
END  (via drill 0.61)
  Top 0.254: v55.92,232.08 55.92,234.3 A25.R1 | v64.17,229.54 63.85,229.22 63.85,223.83 v65.44,222.24 | v77.51,222.55 78.78,221.29 v78.78,210.17 | v118.78,206.68 v115.29,210.17 | v131.8,207 132.12,207.31 v132.12,211.76 | v148.31,215.25 v148.31,211.76 | v165.14,228.27 169.26,232.4 169.26,233.67 168.63,234.3 168.63,263.19 171.17,265.74 v173.39,265.74 | v207.68,294.63 216.57,294.63 v216.57,285.74
  Route2 0.254: v173.39,265.74 175.61,267.96 180.06,267.96 187.68,275.58 188.63,275.58 v207.68,294.63
  Route15 0.254: v97.51,210.17 99.1,211.76 101,209.86 101.95,209.86 102.27,209.54 106.08,209.54 106.4,209.22 108.3,209.22 v109.26,210.17 | v148.31,215.25 149.9,216.84 149.26,217.48 149.26,218.43 157.52,226.68 v157.2,227 | v216.57,285.74 231.18,285.74 242.61,297.17 243.56,297.17 268.64,272.09 269.28,272.09 275.63,265.74 275.63,264.78 274.99,264.15 A08.E1
  Bottom 0.254: v55.92,232.08 58.14,229.86 63.85,229.86 v64.17,229.54 | v65.44,222.24 66.71,220.97 75.92,220.97 v77.51,222.55 | v97.51,210.17 v78.78,210.17 | v115.29,210.17 v109.26,210.17 | v118.78,206.68 120.05,205.41 121.32,205.41 121.64,205.09 129.26,205.09 131.16,207 v131.8,207 | v148.31,211.76 v132.12,211.76 | v157.2,227 157.52,227.32 157.83,227.32 158.15,227.64 162.6,227.64 162.91,227.32 164.18,227.32 v165.14,228.27
END\  (via drill 0.61)
  Top 0.254: v286.74,188.9 286.1,189.54 286.1,200.96 285.47,201.6 285.47,209.22 284.83,209.86 284.83,220.97 285.47,221.6 285.47,224.46 285.15,224.78 285.15,227.64 285.79,228.27 285.79,230.49 285.47,230.81 285.47,255.26 v283.88,256.85 | v269.91,244.14 269.59,244.46 269.59,255.58 271.18,257.16 271.18,259.7 A08.F1
  Bottom 0.254: v286.74,188.9 287.06,188.58 315.95,188.58 317.22,189.85 321.35,189.85 321.66,190.17 B04.F1 | v283.88,256.85 282.29,258.43 276.26,258.43 274.67,260.02 272.13,260.02 A08.F1 | v269.91,244.14 268.96,243.19 257.21,243.19 256.26,244.14 A09.M2
ENI  (via drill 0.61)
